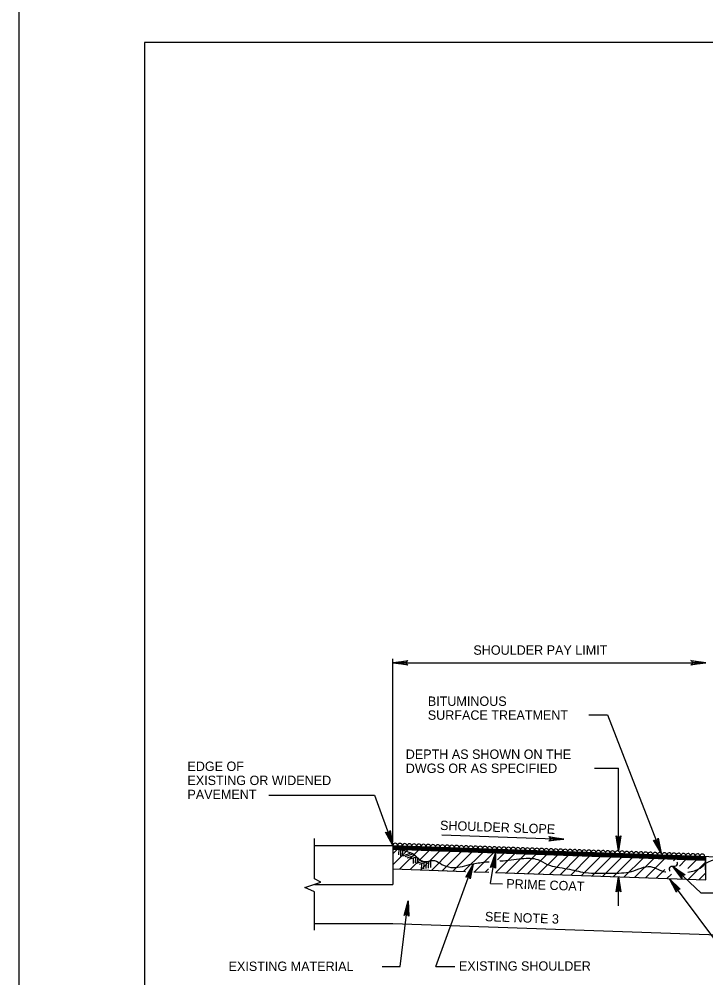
# Model space of a CAD drawing. Extents: x 638216 to 639962, y 297510 to 299292.
# Drawn here: x 638215.9 to 638435.2, y 298384.5 to 298690.7 of the extents above; entities that cross this region are included whole.
import ezdxf

# ---------------------------------------------------------------- set-up
doc = ezdxf.new("R2010")
doc.units = 0
for name, color, linetype in [('1', 7, 'Continuous'), ('2', 7, 'Continuous'), ('3', 7, 'Continuous'), ('PLT-BNDY', 7, 'Continuous')]:
    doc.layers.add(name, color=color, linetype=linetype)

msp = doc.modelspace()

# ---------------------------------------------------------------- linework, layer by layer
at = {"layer": '1'}
msp.add_lwpolyline([(639041.88, 298119.24), (639041.88, 298683.24), (638255.88, 298683.24), (638255.88, 298119.24), (639041.88, 298119.24), (639041.88, 298145.6), (638841.88, 298145.6), (638841.88, 298210.28), (639041.88, 298210.28), (639041.88, 298239.24), (638841.88, 298239.24), (638841.88, 298119.24), (638920.69, 298119.24), (638920.69, 298145.6), (638920.69, 298119.24), (638997.69, 298119.24), (638997.69, 298145.6), (638997.69, 298133.28), (639041.88, 298133.28)], dxfattribs=at)
msp.add_lwpolyline([(639041.88, 298119.24), (639041.88, 298683.24), (638255.88, 298683.24), (638255.88, 298119.24), (639041.88, 298119.24), (639041.88, 298145.6), (638841.88, 298145.6), (638841.88, 298210.28), (639041.88, 298210.28), (639041.88, 298239.24), (638841.88, 298239.24), (638841.88, 298119.24), (638920.69, 298119.24), (638920.69, 298145.6), (638920.69, 298119.24), (638997.69, 298119.24), (638997.69, 298145.6), (638997.69, 298133.28), (639041.88, 298133.28)], dxfattribs=at)
at = {"layer": '2'}
for p, q in [((638335.27, 298427.97), (638335.27, 298486.4)), ((638335.26, 298485.15), (638435.19, 298485.15)), ((638397.8, 298468.55), (638403.76, 298468.55)), ((638403.76, 298468.55), (638421, 298424.36)), ((638399.68, 298451.47), (638407.31, 298451.47)), ((638407.31, 298425.06), (638407.31, 298451.47)), ((638295.67, 298442.9), (638329.41, 298442.9)), ((638329.41, 298442.9), (638335.27, 298426.82)), ((638310.25, 298416.13), (638310.25, 298429.02)), ((638350.86, 298430.15), (638389.85, 298428.76)), ((638310.27, 298426.82), (638335.27, 298426.82)), ((638335.22, 298425.57), (638435.16, 298422.09)), ((638435.16, 298422.09), (638335.22, 298425.57)), ((638335.23, 298425.89), (638408.83, 298423.32)), ((638335.24, 298426.08), (638408.83, 298423.51)), ((638335.25, 298426.37), (638408.83, 298423.8)), ((638335.26, 298426.6), (638408.83, 298424.03)), ((638335.27, 298426.82), (638335.27, 298414.32)), ((638335.27, 298426.82), (638408.83, 298424.26)), ((638335.27, 298425.56), (638335.27, 298419.34)), ((638337.16, 298425.73), (638337.08, 298423.79)), ((638337.73, 298425.32), (638337.64, 298423.41)), ((638338.33, 298425.18), (638338.26, 298423.56)), ((638340.65, 298424.19), (638338.32, 298423.4)), ((638341.51, 298423.97), (638339.04, 298423.12)), ((638342.26, 298423.55), (638339.75, 298422.69)), ((638342.7, 298423.1), (638340.35, 298422.3)), ((638341.78, 298422.65), (638341.7, 298421.03)), ((638342.45, 298422.9), (638342.37, 298421.28)), ((638343.09, 298422.92), (638343.02, 298421.3)), ((638366.42, 298414.66), (638368.02, 298424.34)), ((638408.83, 298424.26), (638472.68, 298422.03)), ((638408.83, 298424.03), (638435.2, 298423.11)), ((638408.83, 298423.8), (638435.19, 298422.88)), ((638408.83, 298423.51), (638435.18, 298422.59)), ((638408.83, 298423.32), (638435.17, 298422.4)), ((638435.2, 298415.83), (638435.16, 298422.09)), ((638435.2, 298415.83), (638435.2, 298423.34)), ((638335.34, 298419.32), (638358.48, 298418.51)), ((638335.34, 298419.32), (638358.31, 298418.52)), ((638344.78, 298421.69), (638342.82, 298421.02)), ((638345.77, 298421.46), (638343.65, 298420.74)), ((638344.4, 298420.82), (638344.32, 298419.1)), ((638345.15, 298421.13), (638345.07, 298419.28)), ((638345.85, 298421.39), (638345.77, 298419.41)), ((638346.6, 298421.63), (638346.51, 298419.52)), ((638347.31, 298421.87), (638347.22, 298419.71)), ((638349.02, 298388.17), (638360.9, 298420.87)), ((638433.58, 298411.66), (638424.65, 298420.11)), ((638361.08, 298418.42), (638365.95, 298418.25)), ((638361.08, 298418.42), (638365.92, 298418.25)), ((638367.99, 298418.18), (638435.2, 298415.83)), ((638368.12, 298418.17), (638435.2, 298415.83)), ((638407.31, 298407.47), (638407.31, 298416.78)), ((638445.25, 298387.11), (638423.56, 298416.16)), ((638310.27, 298414.32), (638335.27, 298414.32)), ((638366.42, 298414.66), (638370.3, 298414.52)), ((638310.19, 298399.7), (638310.19, 298411.98)), ((638433.58, 298411.66), (638438.18, 298411.66)), ((638337.61, 298388.13), (638340.18, 298409.06)), ((638310.27, 298401.82), (638335.27, 298401.82)), ((638335.27, 298401.82), (638519.95, 298395.37)), ((638331.83, 298388.13), (638337.61, 298388.13)), ((638349.02, 298388.17), (638354.99, 298388.17))]:
    msp.add_line(p, q, dxfattribs=at)
for points in [[(638339.8, 298484.58), (638339.64, 298484.91), (638335.26, 298485.15), (638339.8, 298484.58), (638340.04, 298484.38), (638335.26, 298485.15), (638339.63, 298485.37), (638339.79, 298485.69), (638335.26, 298485.15), (638340.04, 298485.91), (638339.79, 298485.69)], [(638430.65, 298485.72), (638430.82, 298485.39), (638435.19, 298485.15), (638430.65, 298485.72), (638430.41, 298485.92), (638435.19, 298485.15), (638430.82, 298484.94), (638430.66, 298484.61), (638435.19, 298485.15), (638430.41, 298484.4), (638430.66, 298484.61)], [(638334.25, 298431.29), (638334, 298431.01), (638335.27, 298426.82), (638334.25, 298431.29), (638334.35, 298431.57), (638335.27, 298426.82), (638333.57, 298430.86), (638333.21, 298430.89), (638335.27, 298426.82), (638332.92, 298431.05), (638333.21, 298430.89)], [(638385.33, 298429.49), (638385.49, 298429.16), (638389.85, 298428.76), (638385.33, 298429.49), (638385.1, 298429.7), (638389.85, 298428.76), (638385.48, 298428.7), (638385.3, 298428.38), (638389.85, 298428.76), (638385.05, 298428.17), (638385.3, 298428.38)], [(638407.88, 298429.6), (638407.55, 298429.43), (638407.31, 298425.06), (638407.88, 298429.6), (638408.08, 298429.83), (638407.31, 298425.06), (638407.1, 298429.43), (638406.77, 298429.59), (638407.31, 298425.06), (638406.55, 298429.83), (638406.77, 298429.59)], [(638419.88, 298428.8), (638419.63, 298428.52), (638421, 298424.36), (638419.88, 298428.8), (638419.98, 298429.09), (638421, 298424.36), (638419.21, 298428.35), (638418.85, 298428.38), (638421, 298424.36), (638418.55, 298428.53), (638418.85, 298428.38)], [(638335.25, 298424.17), (638336.61, 298425.53)], [(638335.32, 298420.7), (638340.02, 298425.41)], [(638337.4, 298419.25), (638343.44, 298425.29)], [(638340.81, 298419.13), (638346.86, 298425.17)], [(638344.23, 298419.01), (638350.27, 298425.05)], [(638347.65, 298418.89), (638353.69, 298424.93)], [(638351.06, 298418.77), (638357.1, 298424.81)], [(638354.48, 298418.65), (638360.52, 298424.69)], [(638357.89, 298418.53), (638363.94, 298424.57)], [(638361.31, 298418.41), (638367.35, 298424.45)], [(638366.72, 298419.95), (638367.07, 298420.07), (638368.02, 298424.34), (638366.72, 298419.95), (638366.48, 298419.76), (638368.02, 298424.34), (638367.52, 298419.99), (638367.82, 298419.78), (638368.02, 298424.34), (638367.99, 298419.51), (638367.82, 298419.78)], [(638368.14, 298418.17), (638374.19, 298424.21)], [(638368.66, 298422.22), (638370.77, 298424.34)], [(638371.56, 298418.05), (638377.6, 298424.1)], [(638374.98, 298417.93), (638381.02, 298423.98)], [(638378.39, 298417.81), (638384.43, 298423.86)], [(638381.81, 298417.7), (638387.85, 298423.74)], [(638385.23, 298417.57), (638391.27, 298423.62)], [(638388.64, 298417.46), (638394.68, 298423.5)], [(638392.06, 298417.34), (638398.1, 298423.38)], [(638395.47, 298417.22), (638401.52, 298423.26)], [(638398.89, 298417.1), (638404.93, 298423.14)], [(638402.3, 298416.98), (638408.35, 298423.02)], [(638405.72, 298416.86), (638411.77, 298422.9)], [(638409.14, 298416.74), (638415.18, 298422.78)], [(638412.55, 298416.62), (638418.6, 298422.66)], [(638415.97, 298416.5), (638422.01, 298422.55)], [(638424.89, 298421.89), (638425.43, 298422.42)], [(638426.77, 298420.23), (638428.85, 298422.31)], [(638429.49, 298419.41), (638432.26, 298422.19)], [(638358.81, 298416.79), (638359.18, 298416.84), (638360.9, 298420.87), (638358.81, 298416.79), (638358.55, 298416.64), (638360.9, 298420.87), (638359.61, 298416.69), (638359.86, 298416.43), (638360.9, 298420.87), (638359.98, 298416.12), (638359.86, 298416.43)], [(638364.73, 298418.29), (638365.78, 298419.34)], [(638419.39, 298416.38), (638422.11, 298419.1)], [(638427.56, 298416.58), (638427.66, 298416.93), (638424.65, 298420.11), (638427.56, 298416.58), (638427.59, 298416.27), (638424.65, 298420.11), (638427.97, 298417.27), (638428.31, 298417.39), (638424.65, 298420.11), (638428.64, 298417.38), (638428.31, 298417.39)], [(638429.64, 298416.02), (638435.17, 298421.55)], [(638310.19, 298411.98), (638307.08, 298413.33), (638312.28, 298415.06), (638310.25, 298416.13)], [(638406.74, 298412.24), (638407.07, 298412.41), (638407.31, 298416.78), (638406.74, 298412.24), (638406.54, 298412.01), (638407.31, 298416.78), (638407.53, 298412.41), (638407.85, 298412.25), (638407.31, 298416.78), (638408.07, 298412.01), (638407.85, 298412.25)], [(638422.8, 298416.26), (638424.2, 298417.66)], [(638425.82, 298412.18), (638425.98, 298412.52), (638423.56, 298416.16), (638425.82, 298412.18), (638425.8, 298411.88), (638423.56, 298416.16), (638426.35, 298412.79), (638426.7, 298412.86), (638423.56, 298416.16), (638427.02, 298412.79), (638426.7, 298412.86)], [(638433.05, 298415.91), (638435.19, 298418.04)], [(638339.07, 298404.62), (638339.41, 298404.75), (638340.18, 298409.06), (638339.07, 298404.62), (638338.84, 298404.42), (638340.18, 298409.06), (638339.87, 298404.7), (638340.17, 298404.5), (638340.18, 298409.06), (638340.35, 298404.23), (638340.17, 298404.5)]]:
    msp.add_lwpolyline(points, dxfattribs=at)
for centre, start in [((638336.01, 298426.73), 8.6519), ((638337.52, 298426.68), 8.6519), ((638339.03, 298426.62), 8.6519), ((638340.54, 298426.57), 8.6519), ((638342.05, 298426.52), 8.6519), ((638343.56, 298426.46), 8.6519), ((638345.06, 298426.41), 8.6519), ((638346.57, 298426.36), 8.6519), ((638348.08, 298426.31), 8.6519), ((638349.59, 298426.25), 8.6519), ((638351.1, 298426.2), 8.6519), ((638352.61, 298426.15), 8.6519), ((638354.12, 298426.1), 8.6519), ((638355.63, 298426.04), 8.6519), ((638357.13, 298425.99), 8.6519), ((638358.64, 298425.94), 8.6519), ((638360.15, 298425.88), 8.6519), ((638361.66, 298425.83), 8.6519), ((638363.17, 298425.78), 8.6519), ((638364.68, 298425.73), 8.6519), ((638366.19, 298425.67), 8.6519), ((638367.7, 298425.62), 8.6519), ((638369.21, 298425.57), 8.6519), ((638370.71, 298425.52), 8.6519), ((638372.22, 298425.46), 8.6519), ((638373.73, 298425.41), 8.6519), ((638375.24, 298425.36), 8.6519), ((638376.75, 298425.31), 8.6519), ((638378.26, 298425.25), 8.6519), ((638379.77, 298425.2), 8.6519), ((638381.28, 298425.15), 8.6519), ((638382.78, 298425.09), 8.6519), ((638384.29, 298425.04), 8.6519), ((638385.8, 298424.99), 8.6519), ((638387.31, 298424.94), 8.6519), ((638388.82, 298424.88), 8.6519), ((638390.33, 298424.83), 8.6519), ((638391.84, 298424.78), 8.6519), ((638393.35, 298424.73), 8.6519), ((638394.86, 298424.67), 8.6519), ((638396.36, 298424.62), 8.6519), ((638397.87, 298424.57), 8.6519), ((638399.38, 298424.51), 8.6519), ((638400.89, 298424.46), 8.6519), ((638402.4, 298424.41), 8.6519), ((638403.91, 298424.36), 8.6519), ((638405.42, 298424.3), 5.1176), ((638406.96, 298424.32), 5.1176), ((638408.48, 298424.28), 5.1176), ((638409.94, 298424.15), 8.6519), ((638411.45, 298424.09), 8.6519), ((638412.96, 298424.04), 8.6519), ((638414.47, 298423.99), 8.6519), ((638415.98, 298423.94), 8.6519), ((638417.49, 298423.88), 8.6519), ((638419, 298423.83), 8.6519), ((638420.51, 298423.78), 8.6519), ((638422.01, 298423.72), 8.6519), ((638423.52, 298423.67), 8.6519), ((638425.03, 298423.62), 8.6519), ((638426.54, 298423.57), 8.6519), ((638428.05, 298423.51), 8.6519), ((638429.56, 298423.46), 8.6519), ((638431.07, 298423.41), 8.6519), ((638432.58, 298423.36), 8.6519), ((638434.08, 298423.3), 8.6519)]:
    msp.add_arc(centre, 0.762, start, 176.7199, dxfattribs=at)
for points in [[(638335.28, 298426.6), (638338.29, 298425.29), (638342.17, 298423.78), (638344.77, 298421.73), (638348.55, 298421.95), (638350.93, 298420.76), (638353.72, 298419.8), (638359.78, 298420.67), (638364.07, 298421.41), (638366.04, 298421.6)], [(638429.45, 298418.28), (638433.43, 298419.58), (638435.26, 298421.09), (638443.05, 298423.14), (638447.99, 298424.77), (638450.59, 298426.47), (638454.05, 298427.88), (638456.61, 298426.92), (638459.76, 298424.42), (638465.59, 298422.17), (638471.04, 298420.25), (638476.11, 298418.84), (638480.76, 298417.56), (638490.03, 298411.95), (638496.5, 298407.52), (638502.76, 298404.92), (638510.1, 298400.4), (638514.84, 298397.58), (638521.32, 298394.79), (638525.97, 298391.97), (638529.95, 298388.54), (638532.96, 298386.81)], [(638369.44, 298421.83), (638369.68, 298421.85), (638376.48, 298422.59), (638381.55, 298422.27), (638384.56, 298420.76), (638390.94, 298419.35), (638396.65, 298418.17), (638405.05, 298417.97), (638411.43, 298418.49), (638417.59, 298420.03), (638422.34, 298418.39), (638422.42, 298418.38)], [(638423.74, 298418.62), (638423.64, 298419.08), (638423.83, 298419.91), (638424.48, 298420.23), (638425.02, 298420.14), (638425.65, 298420.25), (638426.13, 298420.78), (638426.16, 298421.06), (638426.05, 298421.51)]]:
    msp.add_spline(points, degree=3, dxfattribs=at)
at = {"layer": 'PLT-BNDY'}
msp.add_lwpolyline([(638215.88, 298698.24), (639056.88, 298698.24), (639056.88, 298104.24), (638215.88, 298104.24)], close=True, dxfattribs=at)

# ---------------------------------------------------------------- texts
at = {"layer": '3'}
for s, p in [('SHOULDER PAY LIMIT', (638360.97, 298487.71)), ('BITUMINOUS', (638346.41, 298471.38)), ('SURFACE TREATMENT', (638346.41, 298466.94)), ('DEPTH AS SHOWN ON THE', (638339.37, 298454.45)), ('EDGE OF', (638269.63, 298450.59)), ('DWGS OR AS SPECIFIED', (638339.37, 298449.95)), ('EXISTING OR WIDENED', (638269.63, 298446.09)), ('PAVEMENT', (638269.63, 298441.59)), ('EXISTING MATERIAL', (638282.78, 298386.7)), ('EXISTING SHOULDER', (638356.35, 298386.79))]:
    msp.add_text(s, height=3, dxfattribs=at).set_placement(p)
for s, p in [('SHOULDER SLOPE', (638350.28, 298431.76)), ('PRIME COAT', (638371.43, 298413.1)), ('SEE NOTE 3', (638364.62, 298402.62))]:
    msp.add_text(s, height=3, rotation=357.9999, dxfattribs=at).set_placement(p)

doc.saveas('drawing.dxf')
